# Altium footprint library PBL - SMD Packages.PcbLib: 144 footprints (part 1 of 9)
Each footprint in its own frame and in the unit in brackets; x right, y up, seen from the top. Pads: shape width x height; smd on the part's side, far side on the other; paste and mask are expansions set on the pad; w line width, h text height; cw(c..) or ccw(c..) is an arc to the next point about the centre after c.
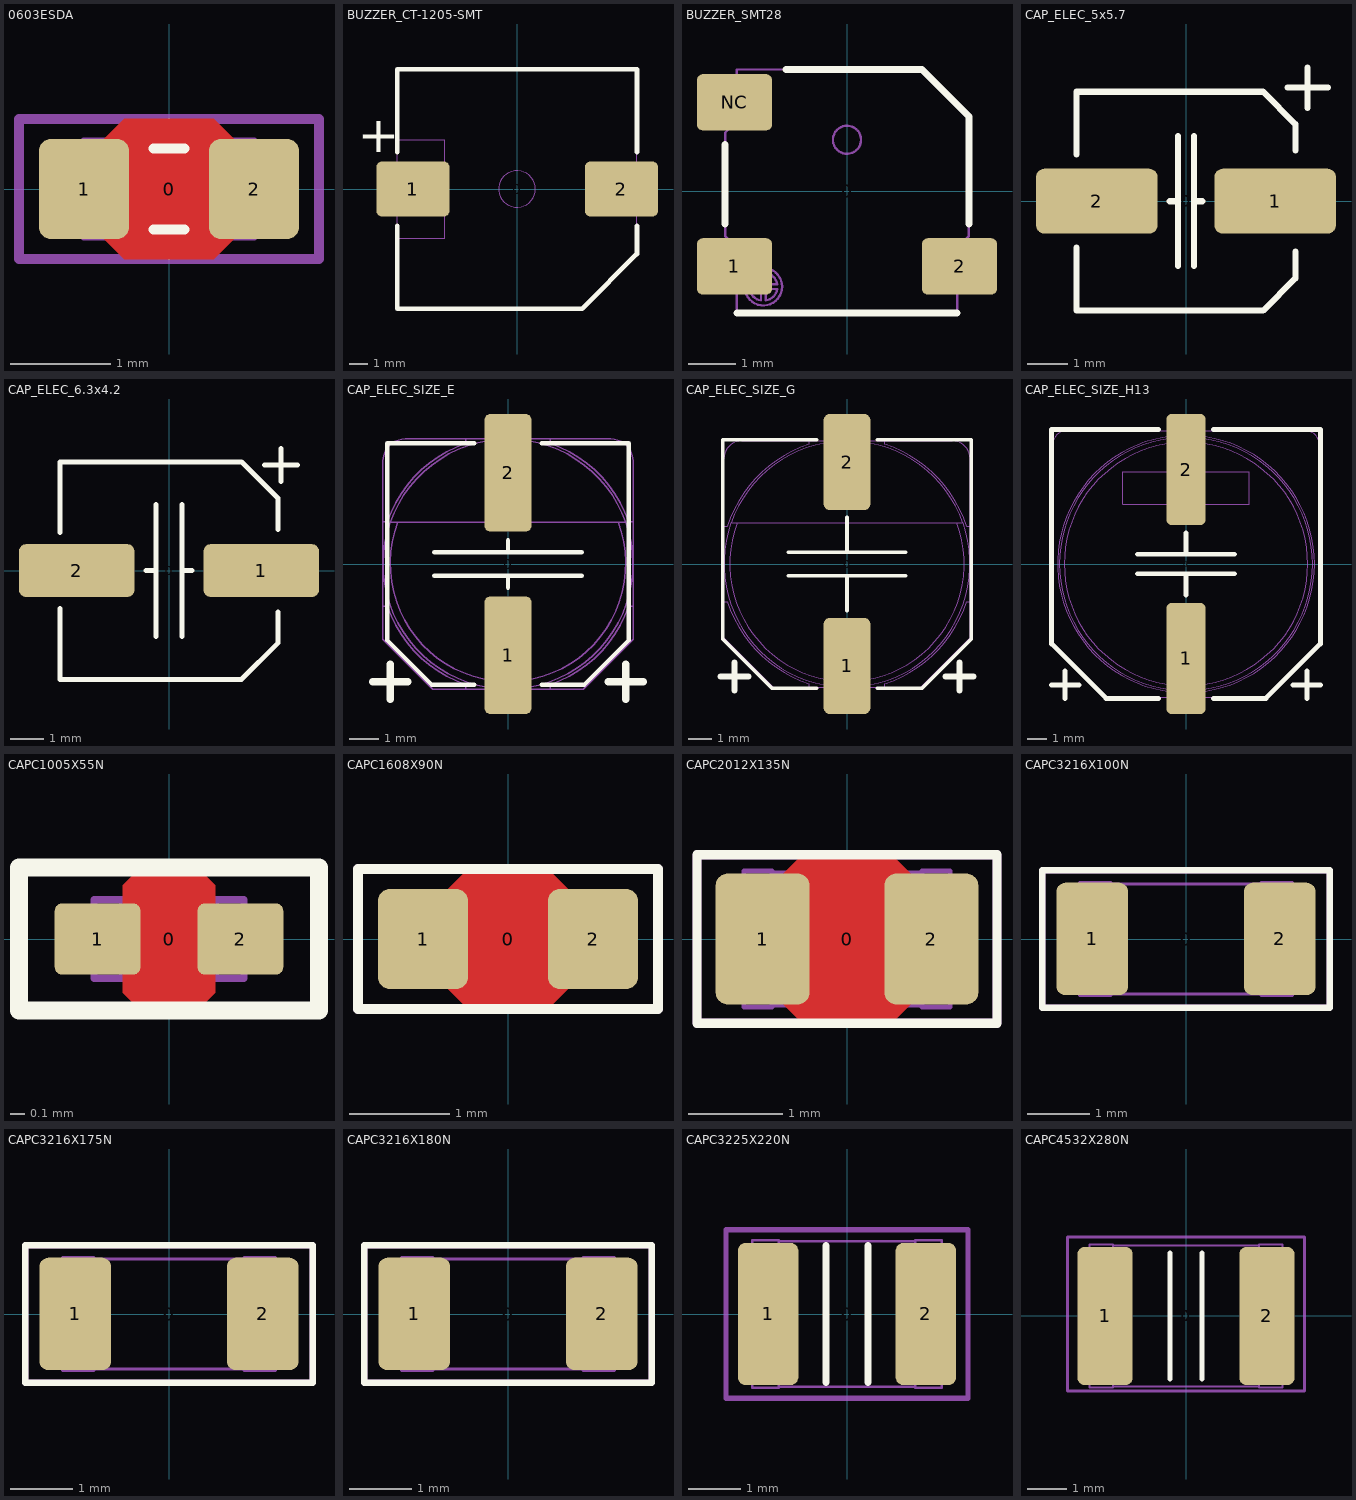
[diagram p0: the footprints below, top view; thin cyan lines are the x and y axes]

## 0603ESDA [mm] "Chip ESD suppressor, Body 1.6x0.8mm, 0603, IPC Medium Density"
height 0.8
pads (3):
  round 0.254 on Mech15: 0(0,0)
  rrect25% 0.9x1 smd: 1(-0.85,0) 2(0.85,0)
Top Layer:
  pour cut-out: -0.65,0.5 -0.45,0.7 0.45,0.7 0.65,0.5 0.65,-0.5 0.45,-0.7 -0.45,-0.7 -0.65,-0.5
Top Overlay:
  lines w0.102: -0.152,-0.406 0.152,-0.406 ; -0.152,0.406 0.152,0.406
13 - 3D Top Side:
  lines w0.076: -0.85,-0.475 0.85,-0.475 0.85,0.475 -0.85,0.475 -0.85,-0.475
15 - Top Courtyards:
  lines w0.1: -1.5,-0.7 1.5,-0.7 1.5,0.7 -1.5,0.7 -1.5,-0.7
3D body "ESD Suppressor 0603 SMD.STEP": height 0.79, standoff -0.01, extent -0.85,-0.45 0.85,0.45

## BUZZER_CT-1205-SMT [mm] "Buzzer SMD sealed 12.8 L x 12.8 W x 7.6mm H 5Vp"
height 7.6
pads (3):
  round 1 on Mech15: 0(0,0)
  rrect20% 4x3 smd: 1(-5.7,0) 2(5.7,0)
Top Overlay:
  lines w0.254: -6.55,-2 -6.55,-6.55 3.55,-6.55 6.55,-3.55 6.55,-2 ; -6.55,2 -6.55,6.55 6.55,6.55 6.55,2
  text "+" at -8.7,2 h2
13 - 3D Top Side:
  circle w0.05: c0,0 r1
  lines w0.05: -6.65,-1.15 -6.65,1.15 ; -6.55,-2.7 -3.95,-2.7 -3.95,2.7 -6.55,2.7 ; -6.55,-1.15 -7.15,-1.15 -7.15,1.15 -6.55,1.15 ; 6.55,-1.15 7.15,-1.15 7.15,1.15 6.55,1.15 ; 6.65,-1.15 6.65,1.15 ; -6.55,-6.55 -6.55,6.55 6.55,6.55 6.55,-3.55 3.55,-6.55 -6.55,-6.55
3D body "CT-1205-SMT.STEP": height 7.6, standoff 0, extent -7.15,-6.55 7.15,6.55

## BUZZER_SMT28 [mm] "Buzzer SMD sealed 5.0 L x 5.0 W x 2.0mm H 5Vp"
height 2.2
pads (4):
  round 0.5 on Mech15: 0(0,0)
  rrect20% 1.6x1.2 smd: 1(-2.4,-1.6) 2(2.4,-1.6) NC(-2.4,1.9)
Top Overlay:
  lines w0.15: -2.6,-0.7 -2.6,1 ; -2.35,-2.6 2.35,-2.6 ; -1.3,2.6 1.6,2.6 2.6,1.6 2.6,-0.7
13 - 3D Top Side:
  circle w0.05: c0,1.1 r0.3
  circle w0.05: c-1.784,-2.034 r0.4
  lines w0.05: -2.65,-1.95 -2.65,-1.25 ; -2.65,1.55 -2.65,2.25 ; -2.35,-1.95 -2.75,-1.95 -2.75,-1.25 -2.35,-1.25 ; -2.35,1.55 -2.75,1.55 -2.75,2.25 -2.35,2.25 ; 2.35,-1.95 2.75,-1.95 2.75,-1.25 2.35,-1.25 ; 2.65,-1.95 2.65,-1.25 ; -2.6,-0.95 -2.6,1.25 -2.35,1.5 -2.35,2.6 1.6,2.6 2.6,1.6 2.6,-0.95 2.35,-1.2 2.35,-2.6 -2.35,-2.6 -2.35,-1.2 -2.6,-0.95 ; -2.08,-2.084 ccw(c-1.784,-2.034) -1.834,-2.33 -1.834,-2.084 -2.08,-2.084 ; -2.08,-1.984 cw(c-1.784,-2.034) -1.834,-1.739 -1.834,-1.984 -2.08,-1.984 ; -1.734,-2.33 ccw(c-1.784,-2.034) -1.489,-2.084 -1.734,-2.084 -1.734,-2.33 ; -1.734,-1.984 -1.489,-1.984 ccw(c-1.784,-2.034) -1.734,-1.739 -1.734,-1.984
3D body "Buzzer SMT28 series.STEP": height 2, standoff 0, extent -2.75,-2.6 2.75,2.6

## CAP_ELEC_5x5.7 [mm] "Capacitor, polarized, aluminum can; 5x5.7mm DxH"
height 5.7
pads (3):
  round 0.508 on Mech15: 0(0,0)
  rrect25% 3x1.6 smd: 1(2.2,0) 2(-2.2,0)
Top Overlay:
  lines w0.152: -2.7,-1.15 -2.7,-2.7 1.9,-2.7 2.7,-1.9 2.7,-1.25 ; -2.7,1.15 -2.7,2.7 1.9,2.7 2.7,1.9 2.7,1.25 ; -0.4,0 -0.2,0 ; -0.2,-1.6 -0.2,1.6 ; 0.2,-1.6 0.2,1.6 ; 0.2,0 0.4,0 ; 2.5,2.8 3,2.8 3.5,2.8 ; 3,2.3 3,3.3
3D body "Cap, elec, 5x5.7_.STEP": height 5.7, standoff 0, extent -2.65,-2.65 2.65,2.65

## CAP_ELEC_6.3x4.2 [mm] "Capacitor, polarized, aluminum can; 6.3x4.2mm DxH"
height 4.2
pads (3):
  round 0.508 on Mech15: 0(0,0)
  rrect25% 3.5x1.6 smd: 1(2.8,0) 2(-2.8,0)
Top Overlay:
  lines w0.152: -3.3,-1.15 -3.3,-3.3 2.2,-3.3 3.3,-2.2 3.3,-1.25 ; -3.3,1.15 -3.3,3.3 2.2,3.3 3.3,2.2 3.3,1.25 ; -0.7,0 -0.5,0 ; -0.4,-2 -0.4,2 ; 0.4,-2 0.4,2 ; 0.5,0 0.7,0 ; 2.9,3.2 3.4,3.2 3.9,3.2 ; 3.4,2.7 3.4,3.7
3D body "Cap, elec, 6.3x4.2.STEP": height 4.23, standoff 0, extent -3.3,-3.3 3.3,3.3

## CAP_ELEC_SIZE_E [mm] "Capacitor, polarized, aluminum can; 8.0x6.2mm DxH"
height 6.2
pads (3):
  round 0.635 on Mech15: 0(0,0)
  rrect25% 1.6x4 smd: 1(0,-3.1) 2(0,3.1)
Top Overlay:
  lines w0.152: -2.5,-0.4 2.5,-0.4 ; -2.5,0.4 2.5,0.4 ; -1.15,-4.1 -2.6,-4.1 -4.1,-2.6 -4.1,4.1 -1.15,4.1 ; 0,-0.8 0,-0.4 ; 0,0.4 0,0.8 ; 1.15,-4.1 2.6,-4.1 4.1,-2.6 4.1,4.1 1.15,4.1
  lines w0.254: -4.6,-4 -3.4,-4 ; -4,-4.6 -4,-3.4 ; 3.4,-4 4.6,-4 ; 4,-4.6 4,-3.4
13 - 3D Top Side:
  lines w0.05: -4.25,-1.436 -4.106,-1.436 ccw(c0,0) -1.436,-4.106 -1.436,-4.25 ; -4.25,1.436 -4.106,1.436 cw(c0,0) -1.436,4.106 -1.436,4.25 ; -4.005,1.417 cw(c0,0) 4.005,1.417 ; -3.741,1.417 ccw(c0,0) 3.741,1.417 ; -0.325,-4.25 -0.325,-4.75 0.325,-4.75 0.325,-4.25 ; -0.325,4.25 -0.325,4.75 0.325,4.75 0.325,4.25 ; 1.436,-4.25 1.436,-4.106 ccw(c0,0) 4.106,-1.436 4.25,-1.436 ; 1.436,4.25 1.436,4.106 cw(c0,0) 4.106,1.436 4.25,1.436 ; -4.25,-2.55 -4.25,3.5 cw(c-3.5,3.5) -3.5,4.25 3.5,4.25 cw(c3.5,3.5) 4.25,3.5 4.25,-2.55 2.55,-4.25 -2.55,-4.25 -4.25,-2.55 ; -4.007,1.417 ccw(c0,0) 4.007,1.417 -4.007,1.417
3D body "CAP Alum Elec Size E.STEP": height 6.5, standoff 0, extent -4.25,-4.75 4.25,4.75

## CAP_ELEC_SIZE_G [mm] "Capacitor, polarized, aluminum can; 10.0x10.2mm DxH"
height 10.2
pads (3):
  round 0.635 on Mech15: 0(0,0)
  rrect25% 2x4.1 smd: 1(0,-4.35) 2(0,4.35)
Top Overlay:
  lines w0.152: -2.5,-0.5 2.5,-0.5 ; -2.5,0.5 2.5,0.5 ; -1.3,-5.3 -3.2,-5.3 -5.3,-3.2 -5.3,5.3 -1.3,5.3 ; 0,-2 0,-0.5 ; 0,0.5 0,2 ; 1.3,-5.3 3.2,-5.3 5.3,-3.2 5.3,5.3 1.3,5.3
  lines w0.254: -5.4,-4.8 -4.2,-4.8 ; -4.8,-5.4 -4.8,-4.2 ; 4.2,-4.8 5.4,-4.8 ; 4.8,-5.4 4.8,-4.2
13 - 3D Top Side:
  lines w0.05: -5.25,-1.601 -5.105,-1.601 ccw(c0,0) -1.601,-5.105 -1.601,-5.25 ; -5.25,1.601 -5.105,1.601 cw(c0,0) -1.601,5.105 -1.601,5.25 ; -4.948,1.75 cw(c0,0) 4.948,1.75 ; -4.684,1.75 ccw(c0,0) 4.684,1.75 ; -0.45,-5.25 -0.45,-6 0.45,-6 0.45,-5.25 ; -0.45,5.25 -0.45,6 0.45,6 0.45,5.25 ; 1.601,-5.25 1.601,-5.105 ccw(c0,0) 5.105,-1.601 5.25,-1.601 ; 1.601,5.25 1.601,5.105 cw(c0,0) 5.105,1.601 5.25,1.601 ; -5.25,-3.15 -3.15,-5.25 3.15,-5.25 5.25,-3.15 5.25,4.5 ccw(c4.5,4.5) 4.5,5.25 -4.5,5.25 ccw(c-4.5,4.5) -5.25,4.5 -5.25,-3.15 ; -4.95,1.75 ccw(c0,0) 4.95,1.75 -4.95,1.75
3D body "CAP Alum Elec Size G.STEP": height 10.5, standoff 0, extent -5.25,-6 5.25,6

## CAP_ELEC_SIZE_H13 [mm] "Capacitor, polarized, aluminum can; 12.5x13.5mm DxH"
height 13.5
pads (3):
  round 0.508 on Mech15: 0(0,0)
  rrect25% 2x5.7 smd: 1(0,-4.85) 2(0,4.85)
Top Overlay:
  lines w0.254: -6.9,-6.2 -5.5,-6.2 ; -6.2,-6.9 -6.2,-5.5 ; -2.5,-0.5 2.5,-0.5 ; -2.5,0.5 2.5,0.5 ; -1.4,-6.9 -4.1,-6.9 -6.9,-4.1 -6.9,6.9 -1.4,6.9 ; 0,-1.6 0,-0.5 ; 0,0.5 0,1.6 ; 1.4,-6.9 4.1,-6.9 6.9,-4.1 6.9,6.9 1.4,6.9 ; 5.5,-6.2 6.9,-6.2 ; 6.2,-6.9 6.2,-5.5
13 - 3D Top Side:
  circle w0.05: c0,0 r6.6
  circle w0.05: c0,0 r6.5
  circle w0.05: c0,0 r6.25
  lines w0.05: -0.45,-6.85 -0.45,-7.5 0.45,-7.5 0.45,-6.85 ; -0.45,6.85 -0.45,7.5 0.45,7.5 0.45,6.85 ; -6.85,-4.11 -4.11,-6.85 4.11,-6.85 6.85,-4.11 6.85,6.1 ccw(c6.1,6.1) 6.1,6.85 -6.1,6.85 ccw(c-6.1,6.1) -6.85,6.1 -6.85,-4.11 ; -3.25,3.055 -3.25,4.745 3.25,4.745 3.25,3.055 -3.25,3.055
3D body "CAP Alum Elec Size H13.STEP": height 14, standoff 0, extent -6.85,-7.5 6.85,7.5

## CAPC1005X55N [mm] "Chip Capacitor, Body 1.0x0.5mm, EIA 0402, IPC Medium Density"
height 0.55
pads (3):
  round 0.2 on Mech15: 0(0,0)
  rrect20% 0.6x0.5 smd: 1(-0.5,0) 2(0.5,0)
Top Layer:
  pour cut-out: -0.325,0.375 -0.2,0.5 0.2,0.5 0.325,0.375 0.325,-0.375 0.2,-0.5 -0.2,-0.5 -0.325,-0.375
Top Overlay:
  lines w0.127: -1.05,-0.5 -1.05,0.5 0.85,0.5 1.05,0.5 1.05,-0.5 -1.05,-0.5
08 - Top ASM Des:
  text ".Designator" at -0.95,-0.25 h0.8
13 - 3D Top Side:
  lines w0.05: -0.325,-0.255 0.325,-0.255 ; -0.325,0.255 0.325,0.255 ; -0.525,-0.275 -0.525,0.275 -0.325,0.275 -0.325,-0.275 -0.525,-0.275 ; 0.325,-0.275 0.525,-0.275 0.525,0.275 0.325,0.275 0.325,-0.275
15 - Top Courtyards:
  lines w0.1: -1.05,-0.5 -1.05,0.5 1.05,0.5 1.05,-0.5 -1.05,-0.5
3D body "CAP 0402 (1005 metric).STEP": height 0.55, standoff 0, extent -0.525,-0.275 0.525,0.275

## CAPC1608X90N [mm] "Chip Capacitor, Body 1.6x0.8mm, EIA 0603, IPC Medium Density"
height 0.9
pads (3):
  round 0.254 on Mech15: 0(0,0)
  rrect25% 0.9x1 smd: 1(-0.85,0) 2(0.85,0)
Top Layer:
  pour cut-out: -0.6,0.5 -0.4,0.7 0.4,0.7 0.6,0.5 0.6,-0.5 0.4,-0.7 -0.4,-0.7 -0.6,-0.5
Top Overlay:
  lines w0.1: -1.5,-0.7 -1.5,0.7 1.5,0.7 1.5,-0.7 -1.5,-0.7
08 - Top ASM Des:
  text ".Designator" at -1.275,-0.3 h1
13 - 3D Top Side:
  lines w0.05: -0.55,-0.43 0.55,-0.43 ; -0.55,0.43 0.55,0.43 ; -0.85,-0.45 -0.55,-0.45 -0.55,0.45 -0.85,0.45 -0.85,-0.45 ; 0.55,-0.45 0.85,-0.45 0.85,0.45 0.55,0.45 0.55,-0.45
15 - Top Courtyards:
  lines w0.1: -1.5,-0.7 1.5,-0.7 1.5,0.7 -1.5,0.7 -1.5,-0.7
3D body "CAP_0603.STEP": height 0.89, standoff -0.01, extent -0.85,-0.45 0.85,0.45

## CAPC2012X135N [mm] "Chip Capacitor, Body 2.0x1.2mm, EIA 0805, IPC Medium Density"
height 1.35
pads (3):
  round 0.254 on Mech15: 0(0,0)
  rrect25% 1x1.4 smd: 1(-0.9,0) 2(0.9,0)
Top Layer:
  pour cut-out: -0.675,0.7 -0.475,0.9 0.475,0.9 0.675,0.7 0.675,-0.7 0.475,-0.9 -0.475,-0.9 -0.675,-0.7
Top Overlay:
  lines w0.1: -1.6,-0.9 1.6,-0.9 1.6,0.9 -1.6,0.9 -1.6,-0.9
08 - Top ASM Des:
  text ".Designator" at -1.4,-0.3 h1
13 - 3D Top Side:
  lines w0.05: -0.8,-0.705 0.8,-0.705 ; -0.8,0.705 0.8,0.705 ; -1.1,-0.725 -1.1,0.725 -0.8,0.725 -0.8,-0.725 -1.1,-0.725 ; 0.8,-0.725 1.1,-0.725 1.1,0.725 0.8,0.725 0.8,-0.725
15 - Top Courtyards:
  lines w0.1: -1.6,-0.9 -1.6,0.9 1.6,0.9 1.6,-0.9 -1.6,-0.9
3D body "CAP_0805.STEP": height 1.34, standoff -0.01, extent -1.1,-0.725 1.1,0.725

## CAPC3216X100N [mm] "Chip Capacitor, Body 3.2x1.6mm, 1.0mm H, EIA 1206, IPC Medium Density"
height 1
pads (3):
  round 0.508 on Mech15: 0(0,0)
  rrect25% 1.15x1.8 smd: 1(-1.5,0) 2(1.5,0)
Top Overlay:
  lines w0.1: -2.3,-1.1 2.3,-1.1 2.3,1.1 -2.3,1.1 -2.3,-1.1
08 - Top ASM Des:
  text ".Designator" at -1.5,-0.225 h1
13 - 3D Top Side:
  lines w0.05: -1.2,-0.88 1.2,-0.88 ; -1.2,0.88 1.2,0.88 ; -1.7,-0.9 -1.2,-0.9 -1.2,0.9 -1.7,0.9 -1.7,-0.9 ; 1.2,-0.9 1.7,-0.9 1.7,0.9 1.2,0.9 1.2,-0.9
15 - Top Courtyards:
  lines w0.1: -2.3,-1.1 -2.3,1.1 2.3,1.1 2.3,-1.1 -2.3,-1.1
3D body "CAPC3216X100N - 1206 (3216 metric).STEP": height 1, standoff 0, extent -1.7,-0.9 1.7,0.9

## CAPC3216X175N [mm] "Chip Capacitor, Body 3.2x1.6mm, 1.75mm H, EIA 1206, IPC Medium Density"
height 1.75
pads (3):
  round 0.508 on Mech15: 0(0,0)
  rrect25% 1.15x1.8 smd: 1(-1.5,0) 2(1.5,0)
Top Overlay:
  lines w0.1: -2.3,-1.1 2.3,-1.1 2.3,1.1 -2.3,1.1 -2.3,-1.1
08 - Top ASM Des:
  text ".Designator" at -2.025,-0.3 h1
13 - 3D Top Side:
  lines w0.05: -1.2,-0.88 1.2,-0.88 ; -1.2,0.88 1.2,0.88 ; -1.7,-0.9 -1.2,-0.9 -1.2,0.9 -1.7,0.9 -1.7,-0.9 ; 1.2,-0.9 1.7,-0.9 1.7,0.9 1.2,0.9 1.2,-0.9
15 - Top Courtyards:
  lines w0.1: -2.3,-1.1 -2.3,1.1 2.3,1.1 2.3,-1.1 -2.3,-1.1
3D body "CAPC3216X175N - 1206 (3216 metric).STEP": height 1.75, standoff 0, extent -1.7,-0.9 1.7,0.9

## CAPC3216X180N [mm] "Chip Capacitor, Body 3.2x1.6mm, 1.8mm H, EIA 1206, IPC Medium Density"
height 1.8
pads (3):
  round 0.508 on Mech15: 0(0,0)
  rrect25% 1.15x1.8 smd: 1(-1.5,0) 2(1.5,0)
Top Overlay:
  lines w0.1: -2.3,-1.1 -2.3,1.1 2.3,1.1 2.3,-1.1 -2.3,-1.1
08 - Top ASM Des:
  text ".Designator" at -1.875,-0.3 h1
13 - 3D Top Side:
  lines w0.05: -1.2,-0.88 1.2,-0.88 ; -1.2,0.88 1.2,0.88 ; -1.7,-0.9 -1.7,0.9 -1.2,0.9 -1.2,-0.9 -1.7,-0.9 ; 1.2,-0.9 1.2,0.9 1.7,0.9 1.7,-0.9 1.2,-0.9
15 - Top Courtyards:
  lines w0.1: -2.3,-1.1 2.3,-1.1 2.3,1.1 -2.3,1.1 -2.3,-1.1
3D body "CAPC3216X180N - 1206 (3216 metric).STEP": height 1.8, standoff 0, extent -1.7,-0.9 1.7,0.9

## CAPC3225X220N [mm] "Chip Capacitor, Body 3.2x2.5mm, EIA 1210, IPC Medium Density"
height 2.2
pads (3):
  round 0.508 on Mech15: 0(0,0)
  rrect25% 1.15x2.7 smd: 1(-1.5,0) 2(1.5,0)
Top Overlay:
  lines w0.127: -0.4,-1.3 -0.4,1.3 ; 0.4,-1.3 0.4,1.3
08 - Top ASM Des:
  text ".Designator" at -2.05,-0.35 h1.27
13 - 3D Top Side:
  lines w0.05: -1.3,-1.38 1.3,-1.38 ; -1.3,1.38 1.3,1.38 ; -1.8,-1.4 -1.8,1.4 -1.3,1.4 -1.3,-1.4 -1.8,-1.4 ; 1.3,-1.4 1.8,-1.4 1.8,1.4 1.3,1.4 1.3,-1.4
15 - Top Courtyards:
  lines w0.1: -2.3,-1.6 2.3,-1.6 2.3,1.6 -2.3,1.6 -2.3,-1.6
3D body "CAP_1210.STEP": height 2.19, standoff -0.01, extent -1.8,-1.4 1.8,1.4

## CAPC4532X280N [mm] "Chip Capacitor, Body 4.5x3.2mm, 1812, IPC Medium Density"
height 2.8
pads (3):
  round 0.508 on Mech15: 0(0,0)
  rrect25% 1.4x3.5 smd: 1(-2.05,0) 2(2.05,0)
Top Overlay:
  lines w0.127: -0.4,-1.6 -0.4,1.6 ; 0.4,-1.6 0.4,1.6
13 - 3D Top Side:
  lines w0.05: -1.85,-1.791 1.85,-1.791 ; -1.85,1.791 1.85,1.791 ; -2.45,-1.811 -1.85,-1.811 -1.85,1.811 -2.45,1.811 -2.45,-1.811 ; 1.85,-1.811 1.85,1.811 2.45,1.811 2.45,-1.811 1.85,-1.811
15 - Top Courtyards:
  lines w0.076: -3,-1.9 3,-1.9 3,2 -3,2 -3,-1.9
3D body "CAP_1812.STEP": height 2.79, standoff -0.01, extent -2.45,-1.8 2.45,1.8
